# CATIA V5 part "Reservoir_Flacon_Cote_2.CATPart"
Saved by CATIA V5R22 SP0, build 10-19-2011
Part number: Reservoir_Flacon_Cote
Bounding box of the stored display mesh (mm): x 0 to 5, y -31 to 31, z -150 to 150
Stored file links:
  D:\PER\CAO_PER_MODIF_2025\CAO_PER_pick&place_2024P\Sous_Ensemble_Flacon\Reservoir_Flacon_Cote_2.CATPart
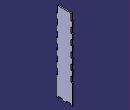
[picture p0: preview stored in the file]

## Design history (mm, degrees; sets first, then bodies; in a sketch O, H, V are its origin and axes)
Body1 (main body)
  Sketch1 on yz-plane, origin (0, 0, 0), H (0, 1, 0), V (0, 0, 1)
    line L1 (-31, 150) -> (31, 150)
    line L2 (31, 150) -> (31, -150)
    line L3 (31, -150) -> (-31, -150)
    line L4 (-31, -150) -> (-31, 150)
    length L4 = 300
    length L1 = 62
    horizontal: L1 H, L3 H
    vertical: L2 V, L4 V
    symmetry: L4 L2 V, L3 L1 H
  Pad1: profile Sketch1, direction (1, 0, 0), length 5
  Sketch2 on end face of Pad1, origin (5, 0, 0), H (0, 1, 0), V (0, 0, 1)
    point P1 (-31, 150)
    line L1 (-31, 150) -> (-26, 150)
    line L2 (-26, 150) -> (-26, 125)
    line L3 (-26, 125) -> (-31, 125)
    line L4 (-31, 125) -> (-31, 150)
    point P2 (-26, 150)
    point P3 (-26, 125)
    point P4 (-31, 125)
    reference projected point E1 (-31, 150) from vertex [face of Pad1 from Sketch1.L1 | end face of Pad1 | face of Pad1 from Sketch1.L4]
    point P5 (31, 150)
    point P6 (26, 150)
    point P7 (26, 125)
    point P8 (31, 125)
    line L5 (31, 150) -> (26, 150)
    line L6 (26, 150) -> (26, 125)
    line L7 (26, 125) -> (31, 125)
    line L8 (31, 125) -> (31, 150)
    length L4 = 25
    length L1 = 5
    horizontal: L1 H, L3 H
    vertical: L2 V, L4 V
    coincidence: P1 E1
    symmetry: P1 P5 V, P2 P6 V, P3 P7 V, P4 P8 V, L1 L5 V, L2 L6 V, L3 L7 V, L4 L8 V
  Pocket1: profile Sketch2, direction (-1, 0, 0), through (limit type 6)
  Sketch3 on end face of Pad1, origin (5, 0, 0), H (0, 1, 0), V (0, 0, 1)
    point P1 (-31, 105)
    line L1 (-31, 105) -> (-26, 105)
    line L2 (-26, 105) -> (-26, 85)
    line L3 (-26, 85) -> (-31, 85)
    line L4 (-31, 85) -> (-31, 105)
    point P2 (-26, 105)
    point P3 (-26, 85)
    point P4 (-31, 85)
    reference projected line E1 (-31, 150) -> (-31, -150) from edge [face of Pad1 from Sketch1.L4 | end face of Pad1]
    reference projected line E2 (-31, 125) -> (-26, 125) from edge [end face of Pad1 | face of Pocket1 from Sketch2.L3]
    point P5 (31, 105)
    point P6 (26, 105)
    point P7 (26, 85)
    point P8 (31, 85)
    line L5 (31, 105) -> (26, 105)
    line L6 (26, 105) -> (26, 85)
    line L7 (26, 85) -> (31, 85)
    line L8 (31, 85) -> (31, 105)
    distance L1 E2 = 20
    length L4 = 20
    length L1 = 5
    horizontal: L1 H, L3 H
    vertical: L2 V, L4 V
    coincidence: L4 E1
    symmetry: P1 P5 V, P2 P6 V, P3 P7 V, P4 P8 V, L1 L5 V, L2 L6 V, L3 L7 V, L4 L8 V
  Pocket2: profile Sketch3, direction (-1, 0, 0), through (limit type 6)
  RectPattern1: of Pocket2, direction 1 instances 5, spacing 40, along edge [face of Pad1 from Sketch1.L4 | end face of Pad1]
  Sketch4 on end face of Pad1, origin (5, 0, 0), H (0, 1, 0), V (0, 0, 1)
    point P1 (-8, -150)
    line L1 (-8, -150) -> (-23, -150)
    line L2 (-23, -150) -> (-23, -145)
    line L3 (-23, -145) -> (-8, -145)
    line L4 (-8, -145) -> (-8, -150)
    point P2 (-23, -150)
    point P3 (-23, -145)
    point P4 (-8, -145)
    reference projected line E1 (-31, -150) -> (31, -150) from edge [face of Pad1 from Sketch1.L3 | end face of Pad1]
    reference projected line E2 (-31, 150) -> (-31, -150) from edge [face of Pad1 from Sketch1.L4 | end face of Pad1]
    point P5 (8, -150)
    point P6 (23, -150)
    point P7 (23, -145)
    point P8 (8, -145)
    line L5 (8, -150) -> (23, -150)
    line L6 (23, -150) -> (23, -145)
    line L7 (23, -145) -> (8, -145)
    line L8 (8, -145) -> (8, -150)
    length L3 = 15
    length L2 = 5
    distance L2 E2 = 8
    horizontal: L1 H, L3 H
    vertical: L2 V, L4 V
    coincidence: L1 E1
    symmetry: P1 P5 V, P2 P6 V, P3 P7 V, P4 P8 V, L1 L5 V, L2 L6 V, L3 L7 V, L4 L8 V
  Pocket3: profile Sketch4, direction (-1, 0, 0), through (limit type 3)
